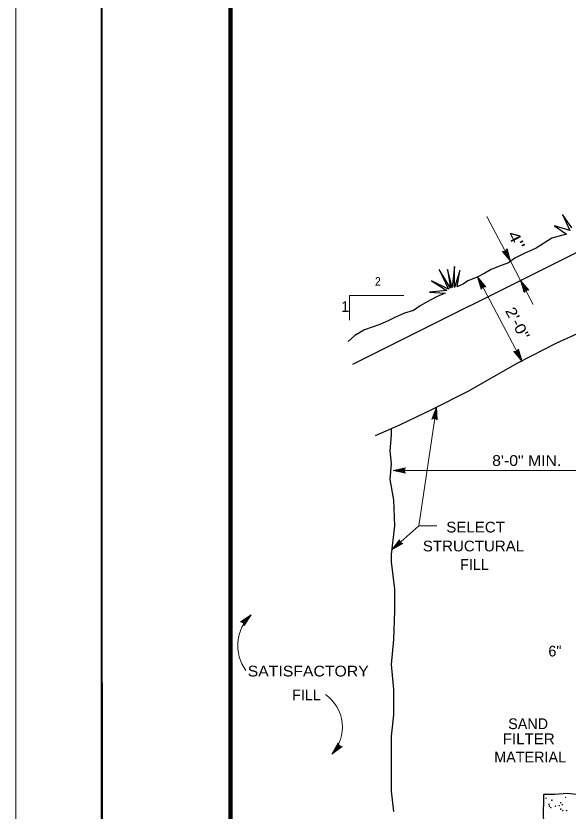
# Model space of a CAD drawing. Extents: x -24.3 to 17.7, y -17.6 to 12.4.
# Drawn here: x -24.34 to -17.91, y -10.05 to -0.8 of the extents above; entities that cross this region are included whole.
import ezdxf
from ezdxf.enums import TextEntityAlignment as Align

# ---------------------------------------------------------------- set-up
doc = ezdxf.new("R2010")
doc.units = 0
doc.header["$LTSCALE"] = 0.05
doc.layers.add('1', color=7, linetype='Continuous', lineweight=13)

msp = doc.modelspace()

# ---------------------------------------------------------------- linework, layer by layer
at = {"layer": '1'}
for p, q in [((-24.34269, -17.6106), (-24.34269, 12.3894)), ((-18.58269, -3.6516), (-18.62269, -3.5096)), ((-18.58269, -3.6516), (-18.67769, -3.5386)), ((-18.66169, -3.5446), (-18.63969, -3.5436)), ((-18.59969, -3.6186), (-18.66169, -3.5446)), ((-18.64669, -3.5516), (-18.63569, -3.5506)), ((-18.61669, -3.5866), (-18.64669, -3.5516)), ((-18.63969, -3.5436), (-18.62569, -3.5266)), ((-18.63569, -3.5506), (-18.62969, -3.5426)), ((-18.61669, -3.5866), (-18.62969, -3.5426)), ((-18.59969, -3.6186), (-18.62569, -3.5266)), ((-18.96569, -3.8356), (-18.92569, -3.9776)), ((-18.94869, -3.8686), (-18.88669, -3.9426)), ((-18.94869, -3.8686), (-18.92269, -3.9606)), ((-18.46469, -3.8756), (-18.36969, -3.9886)), ((-18.46469, -3.8756), (-18.42469, -4.0176)), ((-18.31769, -4.1546), (-18.46469, -3.8756)), ((-18.93169, -3.9006), (-18.91869, -3.9446)), ((-18.93169, -3.9006), (-18.90169, -3.9356)), ((-18.90869, -3.9436), (-18.92269, -3.9606)), ((-18.91269, -3.9366), (-18.91869, -3.9446)), ((-18.90169, -3.9356), (-18.91269, -3.9366)), ((-18.88669, -3.9426), (-18.90869, -3.9436)), ((-18.44769, -3.9086), (-18.38569, -3.9826)), ((-18.44769, -3.9086), (-18.42169, -4.0006)), ((-18.43069, -3.9406), (-18.41769, -3.9846)), ((-18.43069, -3.9406), (-18.40069, -3.9756)), ((-18.41169, -3.9766), (-18.41769, -3.9846)), ((-18.40069, -3.9756), (-18.41169, -3.9766)), ((-20.45769, -4.0516), (-19.82669, -4.0516)), ((-20.45769, -4.0516), (-20.45769, -4.3386)), ((-18.40769, -3.9836), (-18.42169, -4.0006)), ((-18.38569, -3.9826), (-18.40769, -3.9836)), ((-18.44869, -4.8176), (-18.54369, -4.7046)), ((-18.52769, -4.7106), (-18.50569, -4.7096)), ((-18.46569, -4.7846), (-18.52769, -4.7106)), ((-18.51269, -4.7176), (-18.50169, -4.7166)), ((-18.48269, -4.7526), (-18.51269, -4.7176)), ((-18.50569, -4.7096), (-18.49169, -4.6926)), ((-18.50169, -4.7166), (-18.49569, -4.7086)), ((-18.48269, -4.7526), (-18.49569, -4.7086)), ((-18.46569, -4.7846), (-18.49169, -4.6926)), ((-18.44869, -4.8176), (-18.48869, -4.6756)), ((-19.65069, -6.7336), (-19.44569, -5.3526)), ((-19.44569, -5.3526), (-19.49769, -5.4906)), ((-19.44569, -5.3526), (-19.43569, -5.4996)), ((-19.45069, -5.3896), (-19.48469, -5.4796)), ((-19.45669, -5.4246), (-19.47169, -5.4676)), ((-19.45669, -5.4246), (-19.45269, -5.4706)), ((-19.45069, -5.3896), (-19.44469, -5.4856)), ((-19.46369, -5.4736), (-19.48469, -5.4796)), ((-19.46269, -5.4656), (-19.47169, -5.4676)), ((-19.44469, -5.4856), (-19.46369, -5.4736)), ((-19.45269, -5.4706), (-19.46269, -5.4656)), ((-19.95069, -6.0876), (-19.80669, -6.0566)), ((-19.95069, -6.0876), (-16.95069, -6.0876)), ((-19.95069, -6.0876), (-19.80669, -6.1186)), ((-19.91369, -6.0876), (-19.81969, -6.0676)), ((-19.91369, -6.0876), (-19.81969, -6.1076)), ((-19.87769, -6.0876), (-19.83269, -6.0776)), ((-19.87769, -6.0876), (-19.83269, -6.0966)), ((-19.83269, -6.0776), (-19.83669, -6.0876)), ((-19.83669, -6.0876), (-19.83269, -6.0966)), ((-19.81969, -6.0676), (-19.82869, -6.0876)), ((-19.82869, -6.0876), (-19.81969, -6.1076)), ((-19.65069, -6.7336), (-19.44069, -6.7336)), ((-19.96369, -7.0126), (-19.83569, -6.9396)), ((-19.93569, -6.9876), (-19.87969, -6.9106)), ((-19.93569, -6.9876), (-19.85269, -6.9406)), ((-19.90969, -6.9636), (-19.88269, -6.9266)), ((-19.90969, -6.9636), (-19.86969, -6.9406)), ((-19.88269, -6.9266), (-19.87869, -6.9366)), ((-19.87969, -6.9106), (-19.87269, -6.9316)), ((-19.87869, -6.9366), (-19.86969, -6.9406)), ((-19.87269, -6.9316), (-19.85269, -6.9406)), ((-21.60469, -7.7676), (-21.72669, -7.8496)), ((-21.60469, -7.7676), (-21.68269, -7.8926)), ((-21.63069, -7.7946), (-21.70969, -7.8476)), ((-21.68969, -7.8556), (-21.70969, -7.8476)), ((-21.65569, -7.8206), (-21.69269, -7.8466)), ((-21.68369, -7.8496), (-21.69269, -7.8466)), ((-21.68169, -7.8756), (-21.68969, -7.8556)), ((-21.67969, -7.8596), (-21.68369, -7.8496)), ((-21.63069, -7.7946), (-21.68169, -7.8756)), ((-21.65569, -7.8206), (-21.67969, -7.8596)), ((-20.66269, -9.3886), (-20.59169, -9.2596)), ((-20.66269, -9.3886), (-20.54469, -9.2996)), ((-20.63869, -9.3606), (-20.59169, -9.2766)), ((-20.63869, -9.3606), (-20.56169, -9.3026)), ((-20.61469, -9.3336), (-20.59269, -9.2926)), ((-20.61469, -9.3336), (-20.57869, -9.3056)), ((-20.59269, -9.2926), (-20.58769, -9.3026)), ((-20.59169, -9.2766), (-20.58269, -9.2966)), ((-20.58769, -9.3026), (-20.57869, -9.3056)), ((-20.58269, -9.2966), (-20.56169, -9.3026))]:
    msp.add_line(p, q, dxfattribs=at)
at = {"layer": '1', "lineweight": 25}
msp.add_line((-16.88969, -3.0886), (-20.42169, -4.8536), dxfattribs=at)
at = {"layer": '1', "lineweight": 40}
msp.add_line((-23.34169, -8.5556), (-23.34169, -10.8056), dxfattribs=at)
msp.add_lwpolyline([(-23.34269, -16.6106), (-23.34269, 11.3894), (16.65731, 11.3894), (16.65731, -16.6106)], close=True, dxfattribs=at)
at = {"layer": '1', "lineweight": 90}
msp.add_lwpolyline([(-21.84269, 10.8894), (16.15731, 10.8894), (16.15731, -16.1106), (-21.84269, -16.1106)], close=True, dxfattribs=at)
at = {"layer": '1'}
for points in [[(-18.46469, -3.8756), (-18.58269, -3.6516), (-18.85669, -3.1316)], [(-18.67769, -3.5386), (-18.64369, -3.5366), (-18.62269, -3.5096)], [(-18.44869, -4.8176), (-18.96569, -3.8356), (-18.87069, -3.9486)], [(-18.87069, -3.9486), (-18.90469, -3.9506), (-18.92569, -3.9776)], [(-18.36969, -3.9886), (-18.40369, -3.9906), (-18.42469, -4.0176)], [(-18.54369, -4.7046), (-18.50969, -4.7026), (-18.48869, -4.6756)], [(-19.43569, -5.4996), (-19.46469, -5.4816), (-19.49769, -5.4906)], [(-19.80669, -6.0566), (-19.82069, -6.0876), (-19.80669, -6.1186)], [(-19.65069, -6.7336), (-19.96369, -7.0126), (-19.87669, -6.8936)], [(-19.87669, -6.8936), (-19.86669, -6.9256), (-19.83569, -6.9396)], [(-21.68269, -7.8926), (-21.69469, -7.8616), (-21.72669, -7.8496)], [(-20.59169, -9.2596), (-20.57769, -9.2906), (-20.54469, -9.2996)]]:
    msp.add_lwpolyline(points, dxfattribs=at)
at = {"layer": '1', "lineweight": 25}
for points in [[(-17.86769, -3.2616), (-17.97669, -3.1066), (-17.89069, -3.2926), (-18.06969, -3.2386), (-17.92969, -3.3386), (-18.10069, -3.3856), (-18.28569, -3.5016), (-18.42569, -3.5636)], [(-18.42569, -3.5636), (-18.53069, -3.6146), (-18.60769, -3.6696), (-18.72169, -3.7136), (-18.80969, -3.7466), (-18.88269, -3.7906), (-18.97069, -3.8386), (-19.08069, -3.8796), (-19.12869, -3.9156), (-19.20569, -3.9486), (-19.17269, -3.7616), (-19.23569, -3.9566), (-19.23569, -3.7136), (-19.26069, -3.9566), (-19.31569, -3.7466), (-19.28269, -3.9676), (-19.41469, -3.7466), (-19.30469, -3.9786), (-19.50369, -3.8796), (-19.32369, -3.9926), (-19.52569, -4.0116), (-19.34569, -4.0226), (-19.44469, -4.0666), (-19.55469, -4.1256), (-19.63569, -4.1696), (-19.71269, -4.2246), (-19.81869, -4.2576), (-19.92169, -4.3016), (-19.99869, -4.3416), (-20.10569, -4.3896), (-20.28169, -4.4516), (-20.39569, -4.5176), (-20.47269, -4.5876)], [(-17.06169, -4.1056), (-17.24969, -4.1996), (-17.53069, -4.3716), (-18.04769, -4.6066), (-18.50069, -4.8406), (-19.07969, -5.1696), (-19.48569, -5.3726), (-19.87669, -5.5606), (-20.15869, -5.6856)], [(-19.94269, -10.0566), (-19.97069, -9.8206), (-19.97069, -9.4866), (-19.97069, -9.1806), (-19.94269, -8.9306), (-19.94269, -8.6386), (-19.97069, -8.3466), (-19.94269, -8.0546), (-19.92869, -7.7206), (-19.92869, -7.4706), (-19.97069, -7.1506), (-19.97069, -7.0676), (-19.92869, -6.7336), (-19.94269, -6.4276), (-19.98469, -6.1916), (-19.97069, -6.0106), (-19.98469, -5.8576), (-19.97069, -5.6776), (-19.96769, -5.6006)], [(-18.19469, -11.2756), (-18.20969, -11.1096), (-18.20969, -10.9256), (-18.19869, -10.8466), (-18.18269, -10.6826), (-18.19369, -10.5566), (-18.18269, -10.3986), (-18.19369, -10.2146), (-18.19869, -10.0566), (-18.19369, -9.9406), (-18.19369, -9.8546), (-18.06669, -9.8546), (-17.92469, -9.8456), (-17.73569, -9.8616), (-17.57769, -9.8516), (-17.45169, -9.8456), (-17.34569, -9.8456), (-17.21969, -9.8616), (-17.15169, -9.8676), (-17.07869, -9.8596)]]:
    msp.add_lwpolyline(points, dxfattribs=at)
at = {"layer": '1'}
for centre in [(-18.16969, -9.9036), (-17.94069, -9.8926), (-18.13569, -9.9726), (-18.12969, -9.9956), (-18.10169, -9.9266), (-18.06069, -9.9956), (-18.01569, -9.9896), (-17.99769, -9.9556), (-17.98069, -9.9776), (-18.11269, -10.0126), (-17.99769, -10.0296), (-17.97469, -10.0466), (-17.92969, -10.0466)]:
    msp.add_circle(centre, 0.00361, dxfattribs=at)
for centre, radius, start, end in [((-21.26395, -8.12621), 0.49467, 133.5364, 216.09064), ((-20.99878, -9.07534), 0.45945, 317.01367, 55.5213)]:
    msp.add_arc(centre, radius, start, end, dxfattribs=at)

# ---------------------------------------------------------------- texts
for s, width, p in [('4"', 1.45, (-18.56891, -3.43425)), ('2\'-0"', 1.2, (-18.55651, -4.40357))]:
    msp.add_text(s, height=0.125, rotation=297.787, dxfattribs=dict(at, width=width)).set_placement(p, align=Align.CENTER)
for s, height, width, p in [('2', 0.1, 0.9, (-20.12769, -3.9376)), ('8\'-0" MIN.', 0.125, 1.1, (-18.39369, -6.0346)), ('STRUCTURAL', 0.125, 1.05, (-19.01369, -7.0296)), ('FILTER', 0.125, 1.05, (-18.37019, -9.2736))]:
    msp.add_text(s, height=height, dxfattribs=dict(at, width=width)).set_placement(p, align=Align.CENTER)
for s, p in [('1', (-20.5078, -4.2426)), ('FILL', (-19.00219, -7.2446)), ('FILL', (-20.95919, -8.7626)), ('SAND', (-18.37769, -9.0986)), ('MATERIAL', (-18.35419, -9.4856))]:
    msp.add_text(s, height=0.125, dxfattribs=at).set_placement(p, align=Align.CENTER)
at = {"layer": '1', "width": 1.05}
msp.add_text('SELECT', height=0.125, dxfattribs=at).set_placement((-19.33069, -6.8096))
at = {"layer": '1'}
msp.add_text('6"', height=0.125, dxfattribs=at).set_placement((-18.14169, -8.2526))
at = {"layer": '1', "width": 1.1}
msp.add_text('SATISFACTORY', height=0.125, dxfattribs=at).set_placement((-20.23369, -8.4856), align=Align.RIGHT)

doc.saveas('drawing.dxf')
